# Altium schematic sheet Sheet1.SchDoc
size A
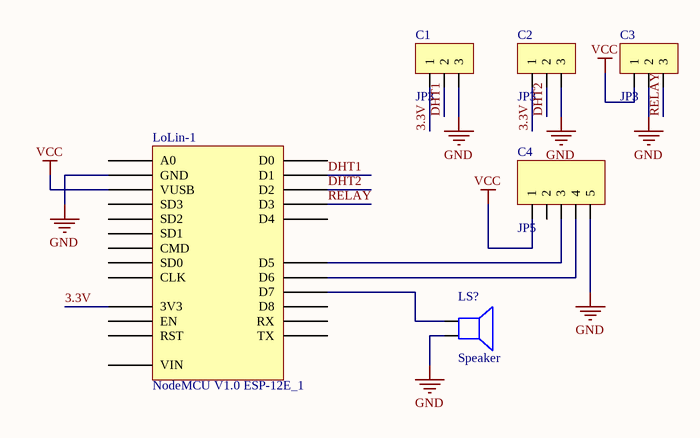
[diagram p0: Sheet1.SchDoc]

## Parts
C1  JP3  [JP3-C1T]
C2  JP3  [JP3-C1T]
C3  JP3  [JP3-C1T]
C4  JP5  [JP5-C1T]
LoLin-1  NodeMCU V1.0 ESP-12E_1  [LoLin NodeMcu V3]
LS?  Speaker  [SPEAKER]

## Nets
GND: C1.3 C2.3 C3.2 C4.5 LoLin-1.GND LS?.2
VCC: C3.1 C4.1 LoLin-1.VUSB
3.3V: C1.1 C2.1 LoLin-1.3V3
DHT1: C1.2 LoLin-1.D1
DHT2: C2.2 LoLin-1.D2
RELAY: C3.3 LoLin-1.D3
NetC4_3: C4.3 LoLin-1.D5
NetC4_4: C4.4 LoLin-1.D6
NetLoLin-1_D7: LoLin-1.D7 LS?.1

Not connected (* = marked no-connect by the designer): C4 2; LoLin-1 A0 CLK CMD D0 D4 D8 EN RST RX SD0 SD1 SD2 SD3 TX VIN

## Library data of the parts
C1-C3 = JP3: WR-PHD 2.54 mm Angled Socket Header; Manufacturer: W¨¹rth Elektronik eiSos GmbH; partNo: 613003143121; ComponentLink1 Description: Manufacturer; ComponentLink2 Description: Datasheet; NoPins: 03
C4 = JP5: WR-PHD 2.54 mm Angled Socket Header; Manufacturer: W¨¹rth Elektronik eiSos GmbH; partNo: 613005143121; ComponentLink1 Description: Manufacturer; ComponentLink2 Description: Datasheet; NoPins: 05
LoLin-1 = NodeMCU V1.0 ESP-12E_1: LoLin NodeMCU V3
LS? = Speaker: Loudspeaker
